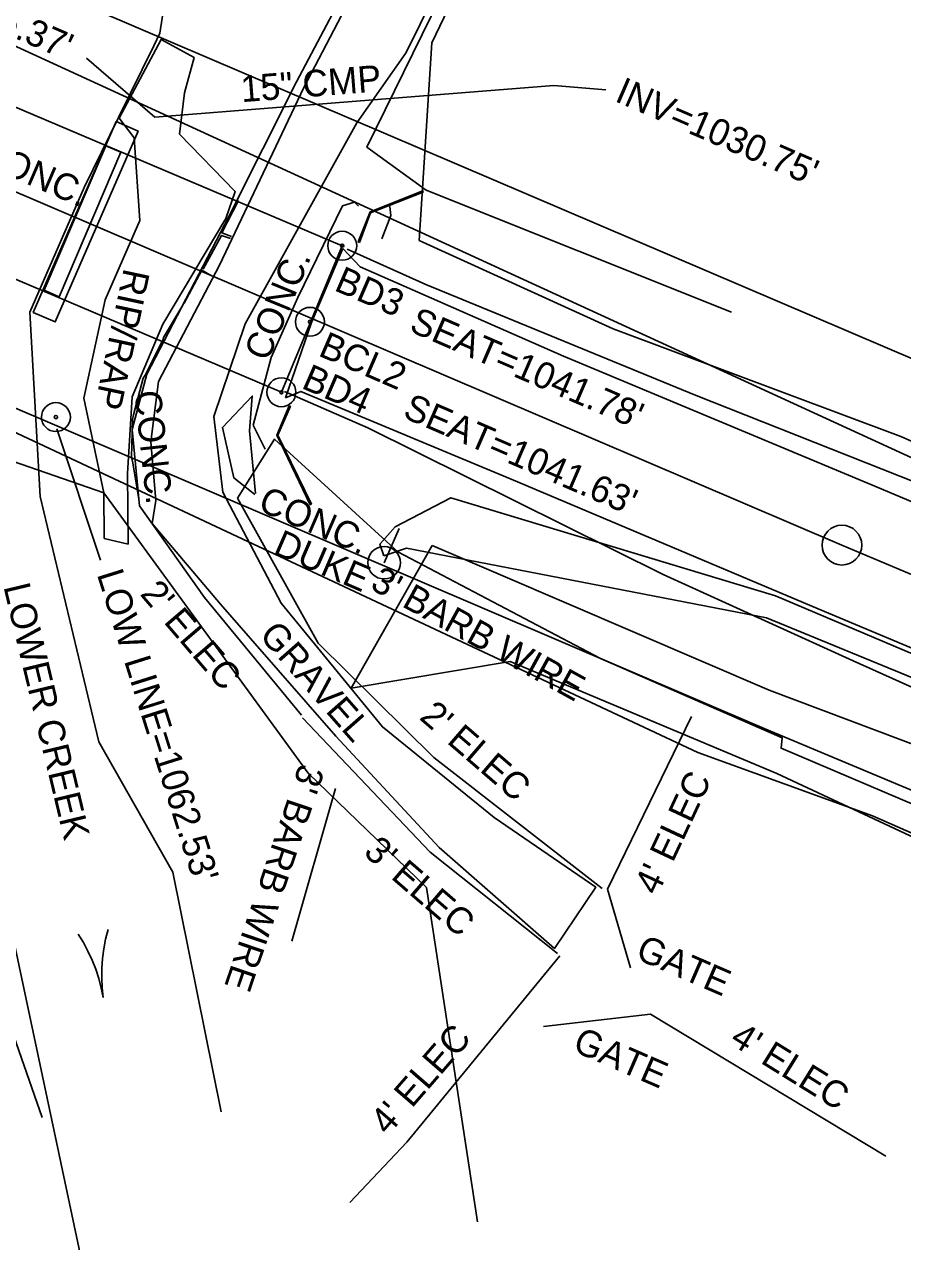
# Model space of a CAD drawing. Extents: x 1230592 to 1231575, y 779497 to 780221.
# Drawn here: x 1231046 to 1231178.4, y 779747 to 779930.4 of the extents above; entities that cross this region are included whole.
import ezdxf

# ---------------------------------------------------------------- set-up
doc = ezdxf.new("R2010")
doc.units = 0
for name, color, linetype in [('Exist Guardrail', 7, 'Continuous'), ('Exist Horizontal Alignment', 7, 'Continuous'), ('Exist Horizontal Alignment Point', 7, 'Continuous'), ('Exist Hydro Stream Flow Arrow CELL', 7, 'Continuous'), ('Exist Hydro Stream or Body of Water', 7, 'Continuous'), ('Exist Hydro Stream or Body of Water Text', 7, 'Continuous'), ('Exist Other Culture Area Outline', 7, 'Continuous'), ('Exist Other Culture Area Outline Text', 7, 'Continuous'), ('Exist Other Culture Fence Line', 7, 'Continuous'), ('Exist Other Culture Fence Line Text', 7, 'Continuous'), ('Exist Other Culture Gate', 7, 'Continuous'), ('Exist Other Culture Gate Text', 7, 'Continuous'), ('Exist Other Culture Located Object CELL', 7, 'Continuous'), ('Exist Other Culture Located Object Text', 7, 'Continuous'), ('Exist Property Line', 7, 'Continuous'), ('Exist Right of Way Line', 7, 'Continuous'), ('Exist Roads EOP', 7, 'Continuous'), ('Exist Roads EOP Other', 7, 'Continuous'), ('Exist Roads EOP Other Text', 7, 'Continuous'), ('Exist Roads Soil', 7, 'Continuous'), ('Exist Roads Soil Text', 7, 'Continuous'), ('Exist Structure Major Bridge Seat Top Elevation', 7, 'Continuous'), ('Exist Structure Major Bridge WW', 7, 'Continuous'), ('Exist Structure Major Deck Tunnel Box Culvert', 7, 'Continuous'), ('Exist Structure Minor Pipes CMP 15 Inch', 7, 'Continuous'), ('Exist Structure Minor Pipes CMP 15 Inch Invert', 7, 'Continuous'), ('Exist Structure Minor Pipes CMP 15 Inch Text', 7, 'Continuous'), ('Exist Utilities Other Located Object CELL', 7, 'Continuous'), ('Exist Utilities Other Located Object Leader', 7, 'Continuous'), ('Exist Utilities Other Located Object Text', 7, 'Continuous'), ('Exist Utilities Power Pole CELL', 7, 'Continuous'), ('Exist Utilities Power Pole Text', 7, 'Continuous'), ('Exist Utilities Sanitary Sewer Forced Main SUE', 7, 'Continuous'), ('Exist Utilities Telephone UG Cable SUE', 7, 'Continuous'), ('Exist Utilities Telephone UG FO SUE', 7, 'Continuous'), ('Exist Utilities Water UG Line SUE', 7, 'Continuous'), ('Exist Vegetation Woods Line', 7, 'Continuous')]:
    doc.layers.add(name, color=color, linetype=linetype)

# ---------------------------------------------------------------- blocks, each defined once
blk = doc.blocks.new('EXIST OTHER CULTURE LOCATED OBJECT')
at = {"layer": 'Exist Other Culture Located Object CELL'}
for radius in [0.0436, 0.0048]:
    blk.add_circle((0, 0), radius, dxfattribs=at)

msp = doc.modelspace()

# ---------------------------------------------------------------- linework, layer by layer
at = {"layer": 'Exist Guardrail'}
for points in [[(1231094.67, 779896.56), (1231106.57, 779891.25), (1231147.08, 779874.58), (1231193.52, 779856.23), (1231225.11, 779845.42)], [(1231212.59, 779815.83), (1231170.99, 779834.49), (1231142.36, 779847.53), (1231097.81, 779869.64), (1231085.25, 779875.1)]]:
    msp.add_lwpolyline(points, dxfattribs=at)
at = {"layer": 'Exist Horizontal Alignment'}
for p, q in [((1230985.56, 779930.45), (1231169.29, 779851.95)), ((1231169.29, 779851.95), (1231365.2, 779769.48))]:
    msp.add_line(p, q, dxfattribs=at)
at = {"layer": 'Exist Horizontal Alignment Point'}
msp.add_circle((1231169.29, 779851.95), 3, dxfattribs=at)
at = {"layer": 'Exist Hydro Stream Flow Arrow CELL'}
msp.add_line((1231057.15, 779788.7), (1231057.15, 779788.7), dxfattribs=at)
for points in [[(1231054.14, 779793.3), (1231054.93, 779792.07), (1231055.6, 779790.73), (1231056.25, 779789.4), (1231056.77, 779788.05), (1231057.22, 779786.64), (1231057.6, 779785.19), (1231057.89, 779783.76)], [(1231058.66, 779793.99), (1231058.27, 779792.57), (1231058.02, 779791.1), (1231057.8, 779789.63), (1231057.7, 779788.19), (1231057.69, 779786.71), (1231057.75, 779785.21), (1231057.89, 779783.76)]]:
    msp.add_lwpolyline(points, dxfattribs=at)
at = {"layer": 'Exist Hydro Stream or Body of Water'}
for points in [[(1231030.61, 779954.52), (1231032.8, 779935.7), (1231027.19, 779896.88), (1231022.2, 779860.88), (1231026.88, 779827.82), (1231039.67, 779791.49), (1231048.72, 779765.68)], [(1231067.83, 779938.22), (1231066.44, 779929.13), (1231065.54, 779927.21), (1231060.22, 779916.41), (1231055.05, 779905.86), (1231046.82, 779887.07), (1231048.39, 779859.3), (1231057.25, 779822.29), (1231068.41, 779802.66), (1231075.7, 779766.51)]]:
    msp.add_lwpolyline(points, dxfattribs=at)
at = {"layer": 'Exist Other Culture Area Outline'}
msp.add_line((1231058.07, 779852.95), (1231061.68, 779852.12), dxfattribs=at)
msp.add_lwpolyline([(1231061.68, 779852.12), (1231061.57, 779862.75), (1231062.28, 779874.28), (1231066.88, 779885.24), (1231076.41, 779901.16), (1231077.82, 779905.23), (1231069.4, 779913.92), (1231070.16, 779920.11), (1231071.62, 779925.46), (1231066.66, 779928.17), (1231060.29, 779916.3), (1231062.56, 779913.36), (1231063.42, 779900.88), (1231058.18, 779888.91), (1231055, 779874.09), (1231057.99, 779859.85), (1231058.07, 779852.95)], dxfattribs=at)
at = {"layer": 'Exist Other Culture Fence Line'}
for p, q in [((1231087.07, 779921.79), (1231104.58, 779954.92)), ((1231106.62, 779905.44), (1231152.64, 779887.06)), ((1231086.35, 779792.25), (1231092.95, 779815.26))]:
    msp.add_line(p, q, dxfattribs=at)
for points in [[(1231106.62, 779905.44), (1231097.65, 779911.94), (1231115.71, 779948.7), (1231133.36, 779983.07), (1231163.63, 779955.4), (1231199.43, 779921.3)], [(1231087.07, 779921.79), (1231076.89, 779901.59), (1231064.5, 779877.73), (1231062.27, 779869.38), (1231063.37, 779857.86)], [(1231078.16, 779859.05), (1231083.71, 779867.91), (1231102.31, 779850.93), (1231132.87, 779834.86)], [(1231087.79, 779826.3), (1231073.16, 779844.04), (1231063.37, 779857.86)], [(1231078.16, 779859.05), (1231090.3, 779837.18), (1231107.76, 779819.94), (1231133.16, 779800.21)], [(1231358.68, 779738.78), (1231341.04, 779744.62), (1231341.83, 779746.77), (1231295.34, 779766.3), (1231295.25, 779764.41), (1231251.39, 779783.37), (1231252.48, 779784.6), (1231212.18, 779801.44), (1231211.6, 779799.44), (1231160.12, 779821.33), (1231160.3, 779822.9), (1231132.87, 779834.86)], [(1231133.92, 779800.08), (1231146.59, 779826.12)], [(1231126.42, 779790.42), (1231107.22, 779805.67), (1231107.22, 779805.67), (1231107.22, 779805.67), (1231087.94, 779825.92)], [(1231095.07, 779752.84), (1231103.7, 779761.97), (1231126.75, 779790.03)], [(1231140.44, 779781.26), (1231175.9, 779759.83)]]:
    msp.add_lwpolyline(points, dxfattribs=at)
at = {"layer": 'Exist Other Culture Gate'}
for points in [[(1231137.42, 779788.22), (1231133.92, 779800.08)], [(1231124.3, 779779.41), (1231140.44, 779781.26)]]:
    msp.add_lwpolyline(points, dxfattribs=at)
at = {"layer": 'Exist Property Line'}
msp.add_line((1231041.41, 779806.38), (1231067.59, 779683.24), dxfattribs=at)
at = {"layer": 'Exist Right of Way Line'}
for p, q in [((1230997.11, 779958.14), (1231181, 779879.57)), ((1230974.01, 779902.76), (1231157.58, 779824.33)), ((1231157.58, 779824.33), (1231353.56, 779741.83))]:
    msp.add_line(p, q, dxfattribs=at)
at = {"layer": 'Exist Roads EOP'}
for points in [[(1231085.4, 779874.13), (1231089.32, 779885.51), (1231094.02, 779896.68)], [(1231369.95, 779778.67), (1231357.05, 779784.21), (1231311.13, 779803.5), (1231265.43, 779822.7), (1231218.7, 779842.17), (1231173.63, 779861.08), (1231127.32, 779880.41), (1231096.67, 779893.88), (1231094.02, 779896.68)], [(1231361.52, 779760.15), (1231348.64, 779765.72), (1231303.18, 779784.92), (1231256.96, 779804.19), (1231211.97, 779822.95), (1231165.7, 779842.33), (1231119.41, 779861.89), (1231087.68, 779875.13), (1231085.4, 779874.13)]]:
    msp.add_lwpolyline(points, dxfattribs=at)
at = {"layer": 'Exist Roads EOP Other'}
msp.add_lwpolyline([(1231059.85, 779915.81), (1231047.35, 779887.04), (1231050.66, 779885.6), (1231063.17, 779914.37)], close=True, dxfattribs=at)
for points in [[(1231078.31, 779903.9), (1231075.81, 779899.02), (1231077.26, 779898.45)], [(1231082.32, 779866.43), (1231080.52, 779870.03), (1231083.23, 779880.21), (1231087.25, 779889.27), (1231093.97, 779903.08), (1231095.77, 779903.65), (1231096.41, 779903.04)], [(1231099.91, 779898.14), (1231101.25, 779901.62), (1231101.13, 779902.98)], [(1231077.09, 779898.15), (1231075.74, 779898.63), (1231072.97, 779893.56)], [(1231073.98, 779892.71), (1231072.79, 779893.42), (1231070.1, 779888.43)], [(1231069.91, 779888.12), (1231067, 779883.27), (1231066.95, 779883.01), (1231064.35, 779877.73), (1231063.93, 779877.14), (1231062.49, 779871.6), (1231062.34, 779870.9), (1231062.18, 779865.14), (1231062.38, 779864.38), (1231063.25, 779858.88)], [(1231080.75, 779859.58), (1231077.6, 779862.08), (1231075.88, 779869.69), (1231080.38, 779874.41), (1231079.96, 779869.17), (1231080.89, 779859.72)]]:
    msp.add_lwpolyline(points, dxfattribs=at)
at = {"layer": 'Exist Roads Soil'}
msp.add_line((1231075.96, 779859.94), (1231084.72, 779843.21), dxfattribs=at)
for points in [[(1231124.47, 780029.83), (1231134.57, 780009.11), (1231131.66, 780004.46), (1231123.57, 779989.24), (1231109.71, 779962.18), (1231088.16, 779920.95)], [(1231096.14, 779915.6), (1231103.5, 779926.08), (1231105.09, 779929.24), (1231118.57, 779957.34), (1231132.94, 779983.82), (1231142.62, 779989.43), (1231148.81, 779990.23), (1231158.63, 779979.4)], [(1231065.3, 779855.2), (1231065.83, 779858.67), (1231065.07, 779867.52), (1231066.23, 779876.61), (1231075.44, 779894.13), (1231088.16, 779920.95)], [(1231096.14, 779915.6), (1231079.32, 779885.33), (1231074.58, 779871.35), (1231075.96, 779859.94)], [(1231065.3, 779855.2), (1231075.57, 779843.06), (1231092.98, 779823.14), (1231108.57, 779806.36), (1231125.93, 779791.17), (1231132.18, 779800.38), (1231116.84, 779810.88), (1231100.01, 779824.54), (1231084.72, 779843.21)]]:
    msp.add_lwpolyline(points, dxfattribs=at)
at = {"layer": 'Exist Structure Major Bridge WW'}
for p, q in [((1231106.17, 779905.15), (1231098.23, 779902.06)), ((1231106.1, 779905.33), (1231106.17, 779905.15)), ((1231096.54, 779897.59), (1231098.23, 779902.06)), ((1231096.36, 779897.69), (1231096.54, 779897.59)), ((1231084.25, 779868.55), (1231086.15, 779872.89)), ((1231085.96, 779872.93), (1231086.15, 779872.89)), ((1231089.31, 779858.12), (1231084.25, 779868.55)), ((1231089.13, 779858.04), (1231089.31, 779858.12))]:
    msp.add_line(p, q, dxfattribs=at)
for points in [[(1231096.36, 779897.69), (1231098.14, 779902.19), (1231106.1, 779905.33)], [(1231085.96, 779872.93), (1231084.09, 779868.52), (1231089.13, 779858.04)]]:
    msp.add_lwpolyline(points, dxfattribs=at)
at = {"layer": 'Exist Structure Major Deck Tunnel Box Culvert'}
for points in [[(1230980.82, 779919.12), (1231084.77, 779874.99), (1231093.94, 779897.08), (1230990.27, 779941.07)], [(1231060.57, 779911.16), (1231051.27, 779889.4), (1231048.98, 779890.37), (1231058.28, 779912.14)]]:
    msp.add_lwpolyline(points, close=True, dxfattribs=at)
at = {"layer": 'Exist Structure Minor Pipes CMP 15 Inch'}
msp.add_line((1231125.85, 779921.21), (1231065.69, 779916.48), dxfattribs=at)
at = {"layer": 'Exist Structure Minor Pipes CMP 15 Inch Invert'}
for points in [[(1231065.69, 779916.48), (1231055.4, 779925.33)], [(1231125.85, 779921.21), (1231133.7, 779920.6)]]:
    msp.add_lwpolyline(points, dxfattribs=at)
at = {"layer": 'Exist Utilities Other Located Object CELL'}
for radius in [2.18, 0.24]:
    msp.add_circle((1231050.77, 779871.25), radius, dxfattribs=at)
at = {"layer": 'Exist Utilities Other Located Object Leader'}
msp.add_line((1231050.91, 779869.47), (1231057.5, 779849.7), dxfattribs=at)
at = {"layer": 'Exist Utilities Power Pole CELL'}
for q in [(1231102.52, 779854.45), (1231100.26, 779849.3)]:
    msp.add_line((1231100.26, 779849.3), q, dxfattribs=at)
msp.add_circle((1231100.26, 779849.3), 2.45, dxfattribs=at)
at = {"layer": 'Exist Utilities Sanitary Sewer Forced Main SUE'}
for points in [[(1230921.98, 779933.17), (1230927.53, 779927.98), (1230943.94, 779916.1), (1231147.57, 779820.67)], [(1231147.57, 779820.67), (1231173.88, 779811.16), (1231214.21, 779793.43), (1231243.53, 779782.39), (1231259.44, 779776.13)]]:
    msp.add_lwpolyline(points, dxfattribs=at)
at = {"layer": 'Exist Utilities Telephone UG Cable SUE'}
msp.add_lwpolyline([(1231100.21, 779850.34), (1231103.62, 779851.47), (1231157.91, 779840.98), (1231205.88, 779821.28), (1231216.34, 779816.85), (1231250.37, 779802.85), (1231299.48, 779783.28), (1231343.46, 779764.91)], dxfattribs=at)
at = {"layer": 'Exist Utilities Telephone UG FO SUE'}
msp.add_lwpolyline([(1231100.21, 779850.34), (1231099.62, 779852.08), (1231101.93, 779854.69), (1231110.33, 779859.1), (1231159.29, 779844.31), (1231206.7, 779824.23), (1231251.36, 779805.47), (1231300.71, 779784.68), (1231344.32, 779766.23)], dxfattribs=at)
at = {"layer": 'Exist Utilities Water UG Line SUE'}
msp.add_lwpolyline([(1230978.2, 779957.72), (1231227.32, 779843.3)], dxfattribs=at)
at = {"layer": 'Exist Vegetation Woods Line'}
for p, q in [((1231105.56, 779897.88), (1231107.46, 779927.68)), ((1231095.28, 779830.4), (1231107.48, 779851.91)), ((1231106.66, 779800.33), (1231114.35, 779749.97))]:
    msp.add_line(p, q, dxfattribs=at)
for points in [[(1231107.46, 779927.68), (1231126.97, 779968.29), (1231178.61, 779952.25), (1231251.71, 779917.22), (1231343.53, 779870.76), (1231396.84, 779847.32)], [(1231360.02, 779788.69), (1231311.8, 779807.41), (1231270.82, 779830.89), (1231223.04, 779848.46), (1231178.15, 779868.3), (1231134.8, 779884.54), (1231105.56, 779897.88)], [(1230974.32, 779888.8), (1231057.99, 779859.85), (1231088.83, 779817.57), (1231106.66, 779800.33)], [(1231107.48, 779851.91), (1231158.34, 779830.07), (1231205.95, 779812.14), (1231252.83, 779793.24), (1231299.52, 779775.45), (1231344.24, 779754.18), (1231364.39, 779751.49)], [(1231358.3, 779733.3), (1231339.79, 779740.73), (1231294.17, 779762.77), (1231250.9, 779782.46), (1231210.44, 779793.71), (1231159.47, 779817.51), (1231119.25, 779834.39), (1231095.28, 779830.4)]]:
    msp.add_lwpolyline(points, dxfattribs=at)

# ---------------------------------------------------------------- block references
at = {"layer": 'Exist Other Culture Located Object CELL', "xscale": 49.99999999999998, "yscale": 49.999999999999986, "rotation": -126.5324575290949}
for p in [(1231093.94, 779897.08), (1231089.08, 779885.61), (1231084.77, 779874.99)]:
    msp.add_blockref('EXIST OTHER CULTURE LOCATED OBJECT', p, dxfattribs=at)

# ---------------------------------------------------------------- texts
at = {"layer": 'Exist Hydro Stream or Body of Water Text'}
msp.add_text('LOWER CREEK', height=4, rotation=283.4625, dxfattribs=at).set_placement((1231042.84, 779845.71))
at = {"layer": 'Exist Other Culture Area Outline Text'}
msp.add_text('RIP/RAP', height=4, rotation=257.9946, dxfattribs=at).set_placement((1231061.04, 779893.81))
at = {"layer": 'Exist Other Culture Fence Line Text'}
for s, rotation, p in [("3' BARB WIRE", 331.1377, (1231097.98, 779845.44)), ("2' ELEC", 310.575, (1231063.33, 779844.52)), ("2' ELEC", 319.2075, (1231105.42, 779825.81)), ("3' BARB WIRE", 251.287, (1231087.54, 779819.2)), ("4' ELEC", 64.9489, (1231141.46, 779799)), ("3' ELEC", 319.2075, (1231096.98, 779805.4)), ("4' ELEC", 49.0416, (1231100.84, 779762.83)), ("4' ELEC", 328.1764, (1231152.2, 779776.88))]:
    msp.add_text(s, height=4, rotation=rotation, dxfattribs=at).set_placement(p)
at = {"layer": 'Exist Other Culture Gate Text'}
for p in [(1231137.99, 779789.68), (1231128.5, 779775.78)]:
    msp.add_text('GATE', height=4, rotation=336.5812, dxfattribs=at).set_placement(p)
at = {"layer": 'Exist Other Culture Located Object Text'}
for s, p in [('BD3', (1231092.56, 779890.42)), ('BCL2', (1231090.17, 779880.57)), ('BD4', (1231087.63, 779875.68))]:
    msp.add_text(s, height=4, rotation=336.5812, dxfattribs=at).set_placement(p)
at = {"layer": 'Exist Roads EOP Other Text'}
for rotation, p in [(336.5812, (1231038.74, 779909.68)), (67.552, (1231082.73, 779879.49)), (276.1498, (1231062.59, 779875.08)), (336.5812, (1231081.05, 779857.29))]:
    msp.add_text('CONC.', height=4, rotation=rotation, dxfattribs=at).set_placement(p)
at = {"layer": 'Exist Roads Soil Text'}
msp.add_text('GRAVEL', height=4, rotation=311.3586, dxfattribs=at).set_placement((1231081.29, 779838.27))
at = {"layer": 'Exist Structure Major Bridge Seat Top Elevation'}
for s, p in [("SEAT=1041.78'", (1231103.86, 779884.27)), ("SEAT=1041.63'", (1231102.9, 779871.27))]:
    msp.add_text(s, height=4, rotation=336.5812, dxfattribs=at).set_placement(p)
at = {"layer": 'Exist Structure Minor Pipes CMP 15 Inch Invert'}
for s, p in [("INV=1025.37'", (1231022.46, 779937.93)), ("INV=1030.75'", (1231134.87, 779918.93))]:
    msp.add_text(s, height=4, rotation=336.5812, dxfattribs=at).set_placement(p)
at = {"layer": 'Exist Structure Minor Pipes CMP 15 Inch Text'}
msp.add_text('15" CMP', height=4, rotation=4.4941, dxfattribs=at).set_placement((1231078.8, 779918.71))
at = {"layer": 'Exist Utilities Other Located Object Text'}
msp.add_text("LOW LINE=1062.53'", height=4, rotation=287.4217, dxfattribs=at).set_placement((1231056.92, 779847.58))
at = {"layer": 'Exist Utilities Power Pole Text'}
msp.add_text('DUKE', height=4, rotation=336.5812, dxfattribs=at).set_placement((1231083.35, 779850.71))

doc.saveas('drawing.dxf')
